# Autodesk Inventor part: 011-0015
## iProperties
Created: 2007-02
Part Number: 011-0015
Material: 34 Cr Mo 4
Document SubType Name: Modeling
Designer: GG5883
Description: Axe de verrouillage
Stock Number: 11-0015
Checked By: GG5883
Author: GG5883
Revision Number: 00
Title: AXE DE VERROUILLOGE
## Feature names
1. Volume base [Revolution]
2. Chanfrein1 [Chamfer]
3. Perçage goupille [Hole]
